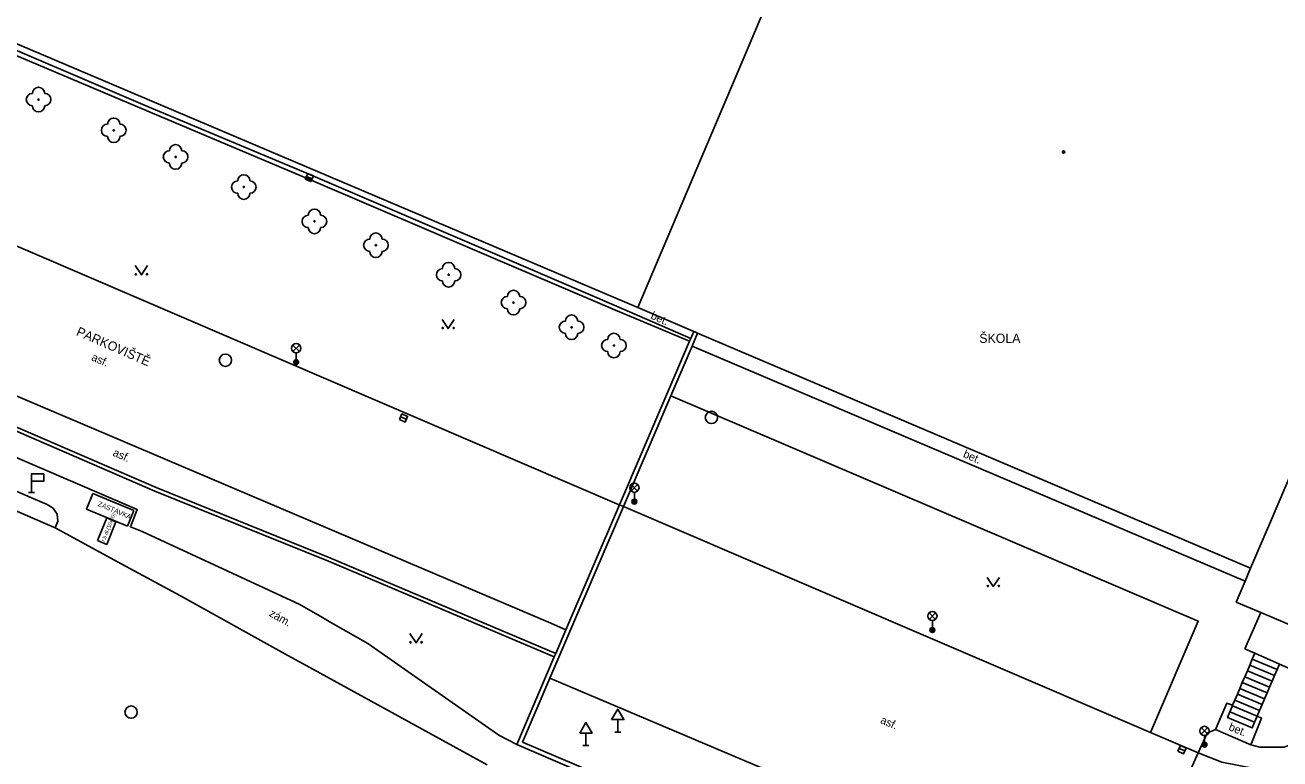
# Model space of a CAD drawing. Extents: x -596024 to -594475, y -1163820 to -1161957.
# Drawn here: x -595045 to -594943.1, y -1162077.2 to -1162017.6 of the extents above; entities that cross this region are included whole.
import ezdxf

# ---------------------------------------------------------------- set-up
doc = ezdxf.new("R2010")
doc.units = 0
for name, color, linetype in [('Level 10', 7, 'Continuous'), ('Level 11', 7, 'Continuous'), ('Level 22', 7, 'Continuous'), ('Level 27', 7, 'Continuous'), ('Level 33', 7, 'Continuous'), ('Level 34', 7, 'Continuous'), ('Level 36', 7, 'Continuous'), ('Level 39', 7, 'Continuous'), ('Level 40', 7, 'Continuous'), ('Level 41', 7, 'Continuous'), ('Level 5', 7, 'Continuous'), ('Level 7', 7, 'Continuous')]:
    doc.layers.add(name, color=color, linetype=linetype)

msp = doc.modelspace()

# ---------------------------------------------------------------- linework, layer by layer
at = {"layer": 'Level 10'}
for points in [[(-595073.95, -1162023.4), (-595071.72, -1162024.36), (-594996.75, -1162056.57)], [(-595002.49, -1162066.11), (-595071.48, -1162036.76)], [(-595079.28, -1162042.64), (-595075.58, -1162044.21), (-595075.2, -1162044.36), (-595074.67, -1162044.64), (-595072.48, -1162045.56), (-595072.13, -1162044.79), (-595071.36, -1162045.13), (-595071.68, -1162045.88), (-595055.85, -1162052.71), (-595042.56, -1162058.45), (-595037.16, -1162061.4)], [(-594996.72, -1162056.58), (-594996.66, -1162056.61), (-594996.4, -1162056.72)], [(-594996.4, -1162056.72), (-594953.57, -1162075.07), (-594949.71, -1162076.72)], [(-595037.16, -1162061.4), (-595032.38, -1162063.98)], [(-595032.38, -1162063.98), (-595023.91, -1162068.67), (-595021.04, -1162070.25), (-595007.46, -1162077.7)], [(-595002.49, -1162066.11), (-595001.08, -1162066.74)], [(-594949.71, -1162076.72), (-594947.78, -1162077.48), (-594945.15, -1162078), (-594942.69, -1162078.02), (-594941.72, -1162077.76), (-594938.84, -1162076.19), (-594936.5, -1162073.41), (-594934.64, -1162069.22)], [(-594971.7, -1162083.67), (-595002.38, -1162070.67)]]:
    msp.add_lwpolyline(points, dxfattribs=at)
at = {"layer": 'Level 11'}
for points in [[(-594991.03, -1162043.27), (-594997.04, -1162040.76), (-595007.15, -1162036.45), (-595021.97, -1162030.11), (-595035.37, -1162024.45), (-595062.36, -1162013), (-595063.35, -1162015.38)], [(-595050.2, -1162017.73), (-595035.26, -1162024.1)], [(-595035.26, -1162024.1), (-595022.4, -1162029.51)], [(-595022.4, -1162029.51), (-595007.03, -1162036.08)], [(-595007.03, -1162036.08), (-594996.96, -1162040.41)], [(-594996.96, -1162040.41), (-594990.93, -1162043.04)], [(-595035.49, -1162058.75), (-595036.46, -1162058.36), (-595035.9, -1162056.96), (-595054.32, -1162049.03), (-595069.91, -1162042.31)], [(-594945.9, -1162062.77), (-594990.82, -1162043.67)], [(-595071.92, -1162044.34), (-595070.32, -1162044.86), (-595055.39, -1162051.32), (-595043.22, -1162056.55)], [(-594992.54, -1162047.7), (-594949.7, -1162066.02), (-594953.57, -1162075.07)], [(-595039.51, -1162055.64), (-595040.03, -1162056.91)], [(-595036.18, -1162057.03), (-595039.51, -1162055.64)], [(-595043.22, -1162056.55), (-595042.72, -1162056.85)], [(-595042.72, -1162056.85), (-595042.41, -1162057.33), (-595042.35, -1162057.91), (-595042.56, -1162058.45)], [(-595040.03, -1162056.91), (-595036.69, -1162058.3)], [(-595036.69, -1162058.3), (-595036.18, -1162057.03)], [(-594996.75, -1162056.57), (-594996.72, -1162056.58)], [(-595039.13, -1162059.48), (-595038.38, -1162059.79), (-595037.64, -1162057.95), (-595038.37, -1162057.64)], [(-595038.37, -1162057.64), (-595039.13, -1162059.48)], [(-595035.49, -1162058.75), (-595022.7, -1162064.68), (-595020.84, -1162065.74), (-595020.16, -1162066.13), (-595017.17, -1162067.85), (-595006.51, -1162075.29), (-595005.06, -1162076.05)], [(-594938.29, -1162067.98), (-594936.45, -1162068.6), (-594936.32, -1162069.09), (-594937.76, -1162072.36), (-594939.37, -1162074.51), (-594939.92, -1162074.99), (-594940.97, -1162075.57), (-594942.71, -1162076.28), (-594944.7, -1162076.27), (-594945.44, -1162076.08)], [(-594945.31, -1162069.11), (-594945.11, -1162068.64)], [(-594945.71, -1162070.06), (-594945.51, -1162069.59)], [(-594945.51, -1162069.59), (-594945.31, -1162069.11)], [(-594945.51, -1162069.59), (-594943.5, -1162070.44)], [(-594945.31, -1162069.11), (-594943.3, -1162069.96)], [(-594943.3, -1162069.96), (-594943.11, -1162069.51)], [(-594946.12, -1162071.01), (-594945.92, -1162070.54)], [(-594945.92, -1162070.54), (-594945.71, -1162070.06)], [(-594945.92, -1162070.54), (-594943.91, -1162071.39)], [(-594945.71, -1162070.06), (-594943.7, -1162070.91)], [(-594943.7, -1162070.91), (-594943.5, -1162070.44)], [(-594943.5, -1162070.44), (-594943.3, -1162069.96)], [(-594946.52, -1162071.96), (-594946.32, -1162071.49)], [(-594946.32, -1162071.49), (-594946.12, -1162071.01)], [(-594946.32, -1162071.49), (-594944.31, -1162072.34)], [(-594946.12, -1162071.01), (-594944.11, -1162071.86)], [(-594944.11, -1162071.86), (-594943.91, -1162071.39)], [(-594943.91, -1162071.39), (-594943.7, -1162070.91)], [(-594948.31, -1162074.84), (-594947.39, -1162072.7), (-594946.91, -1162072.86)], [(-594946.91, -1162072.86), (-594946.73, -1162072.44)], [(-594946.73, -1162072.44), (-594946.52, -1162071.96)], [(-594946.73, -1162072.44), (-594944.72, -1162073.29)], [(-594946.52, -1162071.96), (-594944.51, -1162072.81)], [(-594944.72, -1162073.29), (-594944.51, -1162072.81)], [(-594944.51, -1162072.81), (-594944.31, -1162072.34)], [(-594944.31, -1162072.34), (-594944.11, -1162071.86)], [(-594947.13, -1162073.39), (-594947.32, -1162073.86), (-594945.32, -1162074.71), (-594945.12, -1162074.24)], [(-594946.93, -1162072.91), (-594947.13, -1162073.39)], [(-594947.13, -1162073.39), (-594945.12, -1162074.24)], [(-594946.91, -1162072.86), (-594946.93, -1162072.91)], [(-594946.93, -1162072.91), (-594944.91, -1162073.75)], [(-594945.44, -1162076.08), (-594944.57, -1162073.9), (-594944.91, -1162073.75)], [(-594945.12, -1162074.24), (-594944.91, -1162073.75)], [(-594944.91, -1162073.75), (-594944.72, -1162073.29)], [(-594949.71, -1162076.72), (-594948.97, -1162075.12), (-594948.31, -1162074.84)], [(-594948.31, -1162074.84), (-594945.44, -1162076.08)], [(-594956.01, -1162090.84), (-594949.71, -1162076.72)]]:
    msp.add_lwpolyline(points, dxfattribs=at)
at = {"layer": 'Level 22'}
for centre in [(-595043.92, -1162023.63), (-595037.81, -1162026.13), (-595032.78, -1162028.29), (-595027.24, -1162030.74), (-595021.5, -1162033.53), (-595016.51, -1162035.47), (-595010.6, -1162037.87), (-595005.33, -1162040.13), (-595000.61, -1162042.14), (-594997.17, -1162043.62)]:
    msp.add_circle(centre, 0.05, dxfattribs=at)
for centre, start, end in [((-595043.92, -1162023.13), 0, 180), ((-595044.42, -1162023.63), 90, 270), ((-595043.42, -1162023.63), 270, 90), ((-595043.92, -1162024.13), 180, 0), ((-595038.31, -1162026.13), 90, 270), ((-595037.81, -1162025.63), 0, 180), ((-595037.31, -1162026.13), 270, 90), ((-595037.81, -1162026.63), 180, 0), ((-595033.28, -1162028.29), 90, 270), ((-595032.78, -1162027.79), 0, 180), ((-595032.28, -1162028.29), 270, 90), ((-595032.78, -1162028.79), 180, 0), ((-595027.24, -1162030.24), 0, 180), ((-595027.74, -1162030.74), 90, 270), ((-595026.74, -1162030.74), 270, 90), ((-595027.24, -1162031.24), 180, 0), ((-595022, -1162033.53), 90, 270), ((-595021.5, -1162033.03), 0, 180), ((-595021, -1162033.53), 270, 90), ((-595021.5, -1162034.03), 180, 0), ((-595017.01, -1162035.47), 90, 270), ((-595016.51, -1162034.97), 0, 180), ((-595016.01, -1162035.47), 270, 90), ((-595016.51, -1162035.97), 180, 0), ((-595010.6, -1162037.37), 0, 180), ((-595011.1, -1162037.87), 90, 270), ((-595010.1, -1162037.87), 270, 90), ((-595010.6, -1162038.37), 180, 0), ((-595005.33, -1162039.63), 0, 180), ((-595005.83, -1162040.13), 90, 270), ((-595004.83, -1162040.13), 270, 90), ((-595005.33, -1162040.63), 180, 0), ((-595000.61, -1162041.64), 0, 180), ((-595001.11, -1162042.14), 90, 270), ((-595000.11, -1162042.14), 270, 90), ((-595000.61, -1162042.64), 180, 0), ((-594997.67, -1162043.62), 90, 270), ((-594997.17, -1162043.12), 0, 180), ((-594996.67, -1162043.62), 270, 90), ((-594997.17, -1162044.12), 180, 0)]:
    msp.add_arc(centre, 0.5, start, end, dxfattribs=at)
at = {"layer": 'Level 27'}
for p, q in [((-595022.15, -1162029.87), (-595021.69, -1162030.07)), ((-595014.5, -1162049.41), (-595014.04, -1162049.61)), ((-594951.25, -1162076.37), (-594950.79, -1162076.57))]:
    msp.add_line(p, q, dxfattribs=at)
for points in [[(-595022.25, -1162030.1), (-595021.79, -1162030.3), (-595021.59, -1162029.84), (-595022.05, -1162029.64)], [(-595014.6, -1162049.64), (-595014.14, -1162049.84), (-595013.94, -1162049.38), (-595014.4, -1162049.18)], [(-594951.35, -1162076.6), (-594950.89, -1162076.8), (-594950.69, -1162076.34), (-594951.15, -1162076.14)]]:
    msp.add_lwpolyline(points, close=True, dxfattribs=at)
for centre in [(-595028.74, -1162044.82), (-594989.25, -1162049.47), (-595036.4, -1162073.42)]:
    msp.add_circle(centre, 0.5, dxfattribs=at)
at = {"layer": 'Level 33'}
for p, q in [((-595023.25, -1162044.11), (-595022.72, -1162043.58)), ((-595023.25, -1162043.58), (-595022.72, -1162044.11)), ((-595022.99, -1162044.22), (-595022.99, -1162044.97)), ((-594995.78, -1162055.45), (-594995.25, -1162054.92)), ((-594995.78, -1162054.92), (-594995.25, -1162055.45)), ((-594995.51, -1162055.56), (-594995.51, -1162056.31)), ((-594971.57, -1162065.88), (-594971.04, -1162065.35)), ((-594971.57, -1162065.35), (-594971.04, -1162065.88)), ((-594971.3, -1162065.99), (-594971.3, -1162066.74)), ((-594949.46, -1162075.21), (-594948.93, -1162074.68)), ((-594949.46, -1162074.68), (-594948.93, -1162075.21)), ((-594949.2, -1162075.32), (-594949.2, -1162076.07))]:
    msp.add_line(p, q, dxfattribs=at)
for centre, radius in [((-595022.99, -1162043.84), 0.375), ((-595022.99, -1162044.97), 0.2), ((-595022.99, -1162044.97), 0.145), ((-595022.99, -1162044.97), 0.0876), ((-594995.51, -1162055.18), 0.375), ((-594995.51, -1162056.31), 0.2), ((-594995.51, -1162056.31), 0.145), ((-594995.51, -1162056.31), 0.0876), ((-594971.3, -1162065.61), 0.375), ((-594971.3, -1162066.74), 0.2), ((-594971.3, -1162066.74), 0.145), ((-594971.3, -1162066.74), 0.0876), ((-594949.2, -1162074.95), 0.375), ((-594949.2, -1162076.07), 0.2), ((-594949.2, -1162076.07), 0.145), ((-594949.2, -1162076.07), 0.0876)]:
    msp.add_circle(centre, radius, dxfattribs=at)
at = {"layer": 'Level 34'}
for p, q in [((-595044.49, -1162054.66), (-595044.49, -1162055.56)), ((-595044.74, -1162055.56), (-595044.24, -1162055.56)), ((-594996.86, -1162074.03), (-594996.86, -1162075.05)), ((-594999.45, -1162075.12), (-594999.45, -1162076.14)), ((-594997.11, -1162075.05), (-594996.61, -1162075.05)), ((-594999.7, -1162076.14), (-594999.2, -1162076.14))]:
    msp.add_line(p, q, dxfattribs=at)
for points in [[(-595044.49, -1162054.66), (-595043.49, -1162054.66), (-595043.49, -1162054.06), (-595044.49, -1162054.06)], [(-594997.36, -1162074.03), (-594996.36, -1162074.03), (-594996.86, -1162073.17)], [(-594999.95, -1162075.12), (-594998.95, -1162075.12), (-594999.45, -1162074.26)]]:
    msp.add_lwpolyline(points, close=True, dxfattribs=at)
at = {"layer": 'Level 36'}
for points in [[(-595036.06, -1162037.13), (-595035.56, -1162037.88), (-595035.06, -1162037.13)], [(-595011.14, -1162041.5), (-595010.64, -1162042.25), (-595010.14, -1162041.5)], [(-594966.85, -1162062.47), (-594966.35, -1162063.22), (-594965.85, -1162062.47)], [(-595013.75, -1162067.04), (-595013.25, -1162067.79), (-595012.75, -1162067.04)]]:
    msp.add_lwpolyline(points, dxfattribs=at)
for centre in [(-595036.01, -1162037.83), (-595035.11, -1162037.83), (-595011.09, -1162042.2), (-595010.19, -1162042.2), (-594966.8, -1162063.17), (-594965.9, -1162063.17), (-595013.7, -1162067.74), (-595012.8, -1162067.74)]:
    msp.add_circle(centre, 0.05, dxfattribs=at)
at = {"layer": 'Level 39'}
for radius in [0.09, 0.0398]:
    msp.add_circle((-594960.64, -1162027.89), radius, dxfattribs=at)
at = {"layer": 'Level 5'}
for points in [[(-594986.39, -1162019.73), (-594976.04, -1161995.12)], [(-594995.24, -1162040.54), (-595062.94, -1162011.76)], [(-594995.24, -1162040.54), (-594986.39, -1162019.73)], [(-594990.69, -1162042.48), (-594995.24, -1162040.54)], [(-594990.47, -1162042.57), (-594990.69, -1162042.48)], [(-594990.37, -1162042.61), (-594990.47, -1162042.57)], [(-594945.45, -1162061.71), (-594990.37, -1162042.61)], [(-594940.95, -1162051.2), (-594943.84, -1162057.95)], [(-594943.84, -1162057.95), (-594945.45, -1162061.71)], [(-594945.9, -1162062.77), (-594945.45, -1162061.71)], [(-594946.63, -1162064.47), (-594945.9, -1162062.77)], [(-594944.62, -1162065.33), (-594946.63, -1162064.47)], [(-594945.93, -1162068.27), (-594944.62, -1162065.33)], [(-594939.95, -1162067.29), (-594944.62, -1162065.33)], [(-594945.11, -1162068.64), (-594945.93, -1162068.27)], [(-594943.11, -1162069.51), (-594945.11, -1162068.64)], [(-594941.19, -1162070.35), (-594943.11, -1162069.51)]]:
    msp.add_lwpolyline(points, dxfattribs=at)
at = {"layer": 'Level 7'}
for points in [[(-594996.72, -1162056.58), (-594991.03, -1162043.27)], [(-594991.03, -1162043.27), (-594990.93, -1162043.04)], [(-594990.93, -1162043.04), (-594990.69, -1162042.48)], [(-594990.82, -1162043.67), (-594990.37, -1162042.61)], [(-594996.4, -1162056.72), (-594992.54, -1162047.7), (-594990.82, -1162043.67)], [(-595053.54, -1162047.19), (-595034.48, -1162055.45)], [(-595020.24, -1162060.87), (-595034.37, -1162055.16), (-595053.42, -1162046.93)], [(-595020.36, -1162061.15), (-595034.48, -1162055.45)], [(-595002.38, -1162070.67), (-595000.76, -1162066.88), (-594996.4, -1162056.72)], [(-595001.08, -1162066.74), (-594996.72, -1162056.58)], [(-595002.02, -1162068.93), (-595020.36, -1162061.15)], [(-595001.9, -1162068.65), (-595020.24, -1162060.87)], [(-595001.9, -1162068.65), (-595001.08, -1162066.74)], [(-595002.02, -1162068.93), (-595001.9, -1162068.65)], [(-595005.06, -1162076.05), (-595002.02, -1162068.93)], [(-595004.6, -1162075.86), (-595002.38, -1162070.67)], [(-594973.9, -1162088.96), (-595004.6, -1162075.86)], [(-594974.09, -1162089.42), (-595005.06, -1162076.05)]]:
    msp.add_lwpolyline(points, dxfattribs=at)

# ---------------------------------------------------------------- texts
at = {"layer": 'Level 40'}
for s, height, rotation, p in [('bet.', 0.65, 336.43, (-594994.24, -1162041.42)), ('asf.', 0.65, 336.42, (-595039.68, -1162044.8)), ('asf.', 0.65, 336.37, (-595037.94, -1162052.55)), ('bet.', 0.65, 336.43, (-594968.86, -1162052.67)), ('r.b.dl.(10x20)', 0.3, 68, (-595038.55, -1162059.59)), ('zám.', 0.65, 330.45, (-595025.24, -1162065.57)), ('asf.', 0.65, 336.42, (-594975.58, -1162074.29)), ('bet.', 0.65, 338.02, (-594947.29, -1162074.86))]:
    msp.add_text(s, height=height, rotation=rotation, dxfattribs=at).set_placement(p)
at = {"layer": 'Level 41'}
for s, height, rotation, p in [(' PARKOVIŠTĚ', 0.75, 336.42, (-595041.17, -1162042.65)), ('ZASTÁVKA', 0.4, 337, (-595039.14, -1162056.64))]:
    msp.add_text(s, height=height, rotation=rotation, dxfattribs=at).set_placement(p)
msp.add_text('ŠKOLA', height=0.75, dxfattribs=at).set_placement((-594967.49, -1162043.41))

doc.saveas('drawing.dxf')
